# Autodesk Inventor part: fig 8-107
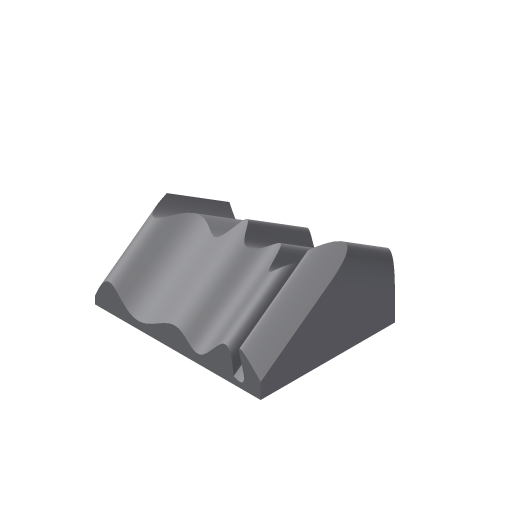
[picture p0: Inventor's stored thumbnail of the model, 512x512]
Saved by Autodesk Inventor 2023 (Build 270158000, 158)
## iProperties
Part Number: fig 8-107
Document SubType Name: Modeling
Created: 2002-12
Designer: deepak
Density: 1 g/cm^3
Material: Generic
Appearance: Default
Control State: 0
Master: False
Checked Out: False
Shininess: 64.0
Length Units: 11269
Angle Units: 11279
Time Units: 11290
Mass Units: 11283
Length Display Precision: 3
Angle Display Precision: 2
Compacted: True
Density: 0.0
Volumn: 0.0
Area: 0.0
PropertySet Name: Model Information
Author: deepak
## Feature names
1. Extrusion1
## Parameters: d1 = 0, d2 = 0, d3 = 0, d4 = 0, d5 = 0
